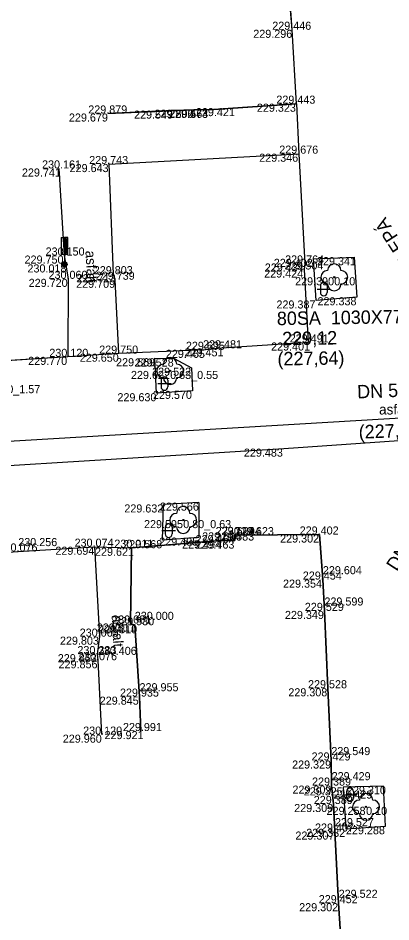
# Model space of a CAD drawing. Extents: x -599516 to -599132, y -1163668 to -1163119.
# Drawn here: x -599440.03 to -599426.15, y -1163390.89 to -1163357.26 of the extents above; entities that cross this region are included whole.
import ezdxf

# ---------------------------------------------------------------- set-up
doc = ezdxf.new("R2010")
doc.units = 0
for name, color, linetype in [('Bod-oznac1', 7, 'Continuous'), ('Bod-oznac2', 7, 'Continuous'), ('Bod-oznac3', 7, 'Continuous'), ('Bod-vyska1', 7, 'Continuous'), ('Bod-vyska2', 7, 'Continuous'), ('Bod-vyska3', 7, 'Continuous'), ('Z_cela-hrobu-horni-linie', 7, 'Continuous'), ('Z_chodnik', 7, 'Continuous'), ('Z_kanalizace-destova', 7, 'Continuous'), ('Z_komunikace', 7, 'Continuous'), ('Z_komunikace-osa', 7, 'Continuous'), ('Z_kultury-znacky', 7, 'Continuous'), ('Z_nove-stromy-prumer-kmene', 7, 'Continuous'), ('Z_obvod-kmene-spodek-ve-vysce1_2m', 7, 'Continuous'), ('Z_popis-budov-povrchu', 7, 'Continuous'), ('Z_stromy-kere', 7, 'Continuous'), ('Z_stromy-nove-vysazene', 7, 'Continuous'), ('Z_vodovod-bez-rozliseni', 7, 'Continuous'), ('Z_znacky-ostatni-orientacni-sloupek', 7, 'Continuous')]:
    doc.layers.add(name, color=color, linetype=linetype)

msp = doc.modelspace()

# ---------------------------------------------------------------- linework, layer by layer
at = {"layer": 'Bod-oznac1'}
for p, q in [((-599429.829, -1163357.692), (-599429.829, -1163357.692)), ((-599429.671, -1163360.443), (-599429.671, -1163360.443)), ((-599436.688, -1163360.808), (-599436.688, -1163360.808)), ((-599434.243, -1163360.699), (-599434.243, -1163360.699)), ((-599433.494, -1163360.666), (-599433.494, -1163360.666)), ((-599433.494, -1163360.668), (-599433.494, -1163360.668)), ((-599432.93, -1163360.669), (-599432.93, -1163360.669)), ((-599432.93, -1163360.67), (-599432.93, -1163360.67)), ((-599432.033, -1163360.607), (-599432.033, -1163360.607)), ((-599429.585, -1163362.303), (-599429.585, -1163362.303)), ((-599438.507, -1163362.853), (-599438.507, -1163362.853)), ((-599436.641, -1163362.689), (-599436.641, -1163362.689)), ((-599438.318, -1163366.094), (-599438.318, -1163366.094)), ((-599429.034, -1163366.216), (-599429.034, -1163366.216)), ((-599427.526, -1163366.153), (-599427.526, -1163366.153)), ((-599438.306, -1163366.424), (-599438.306, -1163366.424)), ((-599429.355, -1163366.389), (-599429.355, -1163366.389)), ((-599436.479, -1163366.789), (-599436.479, -1163366.789)), ((-599429.377, -1163366.613), (-599429.377, -1163366.613)), ((-599428.262, -1163366.902), (-599428.262, -1163366.902)), ((-599438.165, -1163366.961), (-599438.165, -1163366.961)), ((-599436.41, -1163366.995), (-599436.41, -1163366.995)), ((-599428.941, -1163367.765), (-599428.941, -1163367.765)), ((-599427.416, -1163367.646), (-599427.416, -1163367.646)), ((-599433.06, -1163369.603), (-599433.06, -1163369.603)), ((-599432.456, -1163369.546), (-599432.456, -1163369.546)), ((-599429.237, -1163369.33), (-599429.237, -1163369.33)), ((-599438.18, -1163369.864), (-599438.18, -1163369.864)), ((-599436.276, -1163369.746), (-599436.276, -1163369.746)), ((-599434.935, -1163369.915), (-599434.935, -1163369.915)), ((-599434.218, -1163369.927), (-599434.218, -1163369.927)), ((-599433.57, -1163370.268), (-599433.57, -1163370.268)), ((-599434.37, -1163370.388), (-599434.37, -1163370.388)), ((-599434.874, -1163371.217), (-599434.874, -1163371.217)), ((-599433.539, -1163371.129), (-599433.539, -1163371.129)), ((-599430.144, -1163373.279), (-599430.144, -1163373.279)), ((-599433.304, -1163375.288), (-599433.304, -1163375.288)), ((-599434.616, -1163375.356), (-599434.616, -1163375.356)), ((-599433.883, -1163375.939), (-599433.883, -1163375.939)), ((-599433.306, -1163376.589), (-599433.306, -1163376.589)), ((-599431.941, -1163376.496), (-599431.941, -1163376.496)), ((-599428.809, -1163376.476), (-599428.809, -1163376.476)), ((-599437.182, -1163376.93), (-599437.182, -1163376.93)), ((-599435.812, -1163376.968), (-599435.812, -1163376.968)), ((-599434.657, -1163376.687), (-599434.657, -1163376.687)), ((-599432.445, -1163376.697), (-599432.445, -1163376.697)), ((-599431.959, -1163376.701), (-599431.959, -1163376.701)), ((-599440.023, -1163377.108), (-599440.023, -1163377.108)), ((-599428.686, -1163378.154), (-599428.686, -1163378.154)), ((-599428.628, -1163379.319), (-599428.628, -1163379.319)), ((-599435.84, -1163379.788), (-599435.84, -1163379.788)), ((-599435.686, -1163379.853), (-599435.686, -1163379.853)), ((-599437.003, -1163380.277), (-599437.003, -1163380.277)), ((-599437.081, -1163380.928), (-599437.081, -1163380.928)), ((-599437.064, -1163381.155), (-599437.064, -1163381.155)), ((-599428.503, -1163382.198), (-599428.503, -1163382.198)), ((-599435.509, -1163382.509), (-599435.509, -1163382.509)), ((-599436.92, -1163383.924), (-599436.92, -1163383.924)), ((-599435.455, -1163383.791), (-599435.455, -1163383.791)), ((-599428.372, -1163384.886), (-599428.372, -1163384.886)), ((-599428.36, -1163385.82), (-599428.36, -1163385.82)), ((-599427.928, -1163385.885), (-599427.928, -1163385.885)), ((-599426.426, -1163385.84), (-599426.426, -1163385.84)), ((-599428.296, -1163386.505), (-599428.296, -1163386.505)), ((-599427.077, -1163386.61), (-599427.077, -1163386.61)), ((-599427.836, -1163387.428), (-599427.836, -1163387.428)), ((-599426.357, -1163387.332), (-599426.357, -1163387.332)), ((-599428.237, -1163387.531), (-599428.237, -1163387.531)), ((-599428.099, -1163390.196), (-599428.099, -1163390.196))]:
    msp.add_line(p, q, dxfattribs=at)
at = {"layer": 'Bod-oznac2'}
for p, q in [((-599429.829, -1163357.692), (-599429.829, -1163357.692)), ((-599429.671, -1163360.443), (-599429.671, -1163360.443)), ((-599436.688, -1163360.808), (-599436.688, -1163360.808)), ((-599429.585, -1163362.303), (-599429.585, -1163362.303)), ((-599438.507, -1163362.853), (-599438.507, -1163362.853)), ((-599436.641, -1163362.689), (-599436.641, -1163362.689)), ((-599438.318, -1163366.094), (-599438.318, -1163366.094)), ((-599429.355, -1163366.389), (-599429.355, -1163366.389)), ((-599436.479, -1163366.789), (-599436.479, -1163366.789)), ((-599429.377, -1163366.613), (-599429.377, -1163366.613)), ((-599438.165, -1163366.961), (-599438.165, -1163366.961)), ((-599436.41, -1163366.995), (-599436.41, -1163366.995)), ((-599433.06, -1163369.603), (-599433.06, -1163369.603)), ((-599432.456, -1163369.546), (-599432.456, -1163369.546)), ((-599429.237, -1163369.33), (-599429.237, -1163369.33)), ((-599438.18, -1163369.864), (-599438.18, -1163369.864)), ((-599436.276, -1163369.746), (-599436.276, -1163369.746)), ((-599431.941, -1163376.496), (-599431.941, -1163376.496)), ((-599428.809, -1163376.476), (-599428.809, -1163376.476)), ((-599437.182, -1163376.93), (-599437.182, -1163376.93)), ((-599435.812, -1163376.968), (-599435.812, -1163376.968)), ((-599432.445, -1163376.697), (-599432.445, -1163376.697)), ((-599431.959, -1163376.701), (-599431.959, -1163376.701)), ((-599440.023, -1163377.108), (-599440.023, -1163377.108)), ((-599428.686, -1163378.154), (-599428.686, -1163378.154)), ((-599428.628, -1163379.319), (-599428.628, -1163379.319)), ((-599435.84, -1163379.788), (-599435.84, -1163379.788)), ((-599435.686, -1163379.853), (-599435.686, -1163379.853)), ((-599437.003, -1163380.277), (-599437.003, -1163380.277)), ((-599437.081, -1163380.928), (-599437.081, -1163380.928)), ((-599437.064, -1163381.155), (-599437.064, -1163381.155)), ((-599428.503, -1163382.198), (-599428.503, -1163382.198)), ((-599435.509, -1163382.509), (-599435.509, -1163382.509)), ((-599436.92, -1163383.924), (-599436.92, -1163383.924)), ((-599435.455, -1163383.791), (-599435.455, -1163383.791)), ((-599428.372, -1163384.886), (-599428.372, -1163384.886)), ((-599428.36, -1163385.82), (-599428.36, -1163385.82)), ((-599428.296, -1163386.505), (-599428.296, -1163386.505)), ((-599428.237, -1163387.531), (-599428.237, -1163387.531)), ((-599428.099, -1163390.196), (-599428.099, -1163390.196))]:
    msp.add_line(p, q, dxfattribs=at)
at = {"layer": 'Bod-oznac3'}
for p, q in [((-599432.445, -1163376.697), (-599432.445, -1163376.697)), ((-599431.959, -1163376.701), (-599431.959, -1163376.701)), ((-599440.023, -1163377.108), (-599440.023, -1163377.108)), ((-599428.686, -1163378.154), (-599428.686, -1163378.154)), ((-599428.628, -1163379.319), (-599428.628, -1163379.319)), ((-599435.686, -1163379.853), (-599435.686, -1163379.853)), ((-599437.064, -1163381.155), (-599437.064, -1163381.155)), ((-599435.509, -1163382.509), (-599435.509, -1163382.509)), ((-599428.372, -1163384.886), (-599428.372, -1163384.886)), ((-599428.36, -1163385.82), (-599428.36, -1163385.82)), ((-599428.296, -1163386.505), (-599428.296, -1163386.505)), ((-599428.237, -1163387.531), (-599428.237, -1163387.531)), ((-599428.099, -1163390.196), (-599428.099, -1163390.196))]:
    msp.add_line(p, q, dxfattribs=at)
at = {"layer": 'Z_cela-hrobu-horni-linie'}
msp.add_line((-599438.507, -1163362.853), (-599438.318, -1163366.094), dxfattribs=at)
for points in [[(-599432.93, -1163360.669), (-599429.671, -1163360.443), (-599429.829, -1163357.692), (-599429.964, -1163356.071)], [(-599436.688, -1163360.808), (-599433.494, -1163360.666)], [(-599436.479, -1163366.789), (-599436.641, -1163362.689), (-599429.585, -1163362.303), (-599429.355, -1163366.389)], [(-599438.165, -1163366.961), (-599438.18, -1163369.864), (-599442.304, -1163370.125), (-599442.304, -1163370.125), (-599445.172, -1163370.369), (-599445.172, -1163370.369), (-599446.505, -1163370.421), (-599446.505, -1163370.421), (-599449.233, -1163370.571), (-599449.233, -1163370.571), (-599453.602, -1163370.813), (-599456.299, -1163370.964), (-599456.507, -1163366.584), (-599456.695, -1163363.936), (-599454.352, -1163363.803), (-599454.352, -1163363.803)], [(-599429.377, -1163366.613), (-599429.237, -1163369.33), (-599432.456, -1163369.546)], [(-599433.06, -1163369.603), (-599436.276, -1163369.746), (-599436.41, -1163366.995)], [(-599427.935, -1163392.862), (-599428.099, -1163390.196), (-599428.099, -1163390.196), (-599428.237, -1163387.531), (-599428.237, -1163387.531), (-599428.296, -1163386.505), (-599428.296, -1163386.505), (-599428.36, -1163385.82), (-599428.36, -1163385.82), (-599428.372, -1163384.886), (-599428.372, -1163384.886), (-599428.503, -1163382.198), (-599428.628, -1163379.319), (-599428.628, -1163379.319), (-599428.686, -1163378.154), (-599428.686, -1163378.154), (-599428.809, -1163376.476), (-599431.941, -1163376.496), (-599431.959, -1163376.701), (-599431.959, -1163376.701), (-599432.445, -1163376.697), (-599432.445, -1163376.697), (-599435.812, -1163376.968), (-599435.84, -1163379.788), (-599435.686, -1163379.853), (-599435.686, -1163379.853), (-599435.509, -1163382.509), (-599435.509, -1163382.509), (-599435.455, -1163383.791)], [(-599457.167, -1163381.242), (-599457.275, -1163378.053), (-599453.312, -1163377.791), (-599453.312, -1163377.791), (-599450.622, -1163377.661), (-599450.622, -1163377.661), (-599448.1, -1163377.528), (-599448.1, -1163377.528), (-599447.042, -1163377.458), (-599447.042, -1163377.458), (-599446.353, -1163377.412), (-599446.353, -1163377.412), (-599445.292, -1163377.409), (-599445.292, -1163377.409), (-599444.359, -1163377.36), (-599443.693, -1163377.321), (-599442.696, -1163377.276), (-599442.696, -1163377.276), (-599440.023, -1163377.108), (-599440.023, -1163377.108), (-599437.182, -1163376.93), (-599437.003, -1163380.277)], [(-599437.081, -1163380.928), (-599437.064, -1163381.155), (-599437.064, -1163381.155), (-599436.92, -1163383.924)]]:
    msp.add_lwpolyline(points, dxfattribs=at)
at = {"layer": 'Z_chodnik'}
for points in [[(-599429.671, -1163360.443), (-599432.033, -1163360.607), (-599432.93, -1163360.67), (-599433.494, -1163360.668), (-599434.243, -1163360.699), (-599436.688, -1163360.808)], [(-599436.276, -1163369.746), (-599436.41, -1163366.995), (-599436.479, -1163366.789), (-599436.641, -1163362.689), (-599429.585, -1163362.303)], [(-599438.507, -1163362.853), (-599438.318, -1163366.094), (-599438.165, -1163366.961), (-599438.18, -1163369.864)], [(-599437.182, -1163376.93), (-599437.003, -1163380.277), (-599437.081, -1163380.928), (-599437.064, -1163381.155), (-599436.92, -1163383.924)], [(-599435.455, -1163383.791), (-599435.509, -1163382.509), (-599435.686, -1163379.853), (-599435.84, -1163379.788), (-599435.812, -1163376.968)]]:
    msp.add_lwpolyline(points, dxfattribs=at)
at = {"layer": 'Z_kanalizace-destova'}
msp.add_line((-599488.219, -1163375.862), (-599421.433, -1163371.876), dxfattribs=at)
at = {"layer": 'Z_komunikace'}
for points in [[(-599429.671, -1163360.443), (-599429.829, -1163357.692), (-599429.934, -1163356.071), (-599428.132, -1163355.95), (-599428.177, -1163353.182), (-599430.089, -1163353.245), (-599430.127, -1163352.262), (-599430.194, -1163351.431), (-599430.23, -1163350.411), (-599430.239, -1163349.599), (-599430.253, -1163349.42), (-599430.372, -1163346.986), (-599430.362, -1163346.84), (-599430.439, -1163345.534), (-599430.624, -1163342.571), (-599433.698, -1163342.695)], [(-599429.671, -1163360.443), (-599429.585, -1163362.303), (-599429.355, -1163366.389), (-599429.377, -1163366.613), (-599429.237, -1163369.33)], [(-599429.034, -1163366.216), (-599427.526, -1163366.153), (-599427.416, -1163367.646), (-599428.941, -1163367.765), (-599429.034, -1163366.216)], [(-599429.237, -1163369.33), (-599432.456, -1163369.546), (-599433.06, -1163369.603), (-599436.276, -1163369.746), (-599438.18, -1163369.864), (-599440.264, -1163369.997), (-599442.304, -1163370.125), (-599445.172, -1163370.369), (-599446.505, -1163370.421), (-599449.233, -1163370.571)], [(-599434.874, -1163371.217), (-599434.935, -1163369.915), (-599434.218, -1163369.927), (-599433.57, -1163370.268), (-599433.539, -1163371.129), (-599434.874, -1163371.217)], [(-599433.304, -1163375.288), (-599433.306, -1163376.589), (-599434.657, -1163376.687), (-599434.616, -1163375.356)], [(-599433.304, -1163375.288), (-599434.616, -1163375.356)], [(-599457.275, -1163378.053), (-599453.312, -1163377.791), (-599450.622, -1163377.661), (-599448.1, -1163377.528), (-599447.042, -1163377.458), (-599446.353, -1163377.412), (-599445.292, -1163377.409), (-599444.359, -1163377.36), (-599444.351, -1163377.119), (-599443.689, -1163377.085), (-599443.693, -1163377.321), (-599442.696, -1163377.276), (-599440.023, -1163377.108), (-599437.182, -1163376.93), (-599435.812, -1163376.968), (-599432.445, -1163376.697), (-599431.959, -1163376.701), (-599431.941, -1163376.496), (-599428.809, -1163376.476)], [(-599428.809, -1163376.476), (-599428.686, -1163378.154), (-599428.628, -1163379.319), (-599428.503, -1163382.198), (-599428.372, -1163384.886), (-599428.36, -1163385.82), (-599428.296, -1163386.505), (-599428.237, -1163387.531), (-599428.099, -1163390.196), (-599427.935, -1163392.862)], [(-599426.357, -1163387.332), (-599426.426, -1163385.84), (-599427.928, -1163385.885), (-599427.836, -1163387.428), (-599426.357, -1163387.332)]]:
    msp.add_lwpolyline(points, dxfattribs=at)
at = {"layer": 'Z_komunikace-osa'}
msp.add_lwpolyline([(-599486.555, -1163376.352), (-599466.362, -1163375.334), (-599448.228, -1163374.387), (-599430.144, -1163373.279), (-599420.689, -1163372.612)], dxfattribs=at)
at = {"layer": 'Z_kultury-znacky'}
for p, q in [((-599428.777, -1163367.222), (-599428.777, -1163367.472)), ((-599428.527, -1163367.222), (-599428.527, -1163367.472)), ((-599428.902, -1163367.347), (-599428.402, -1163367.347)), ((-599434.833, -1163370.859), (-599434.333, -1163370.859)), ((-599434.708, -1163370.734), (-599434.708, -1163370.984)), ((-599434.458, -1163370.734), (-599434.458, -1163370.984)), ((-599434.675, -1163376.332), (-599434.175, -1163376.332)), ((-599434.55, -1163376.207), (-599434.55, -1163376.457)), ((-599434.3, -1163376.207), (-599434.3, -1163376.457)), ((-599427.801, -1163386.037), (-599427.801, -1163386.287)), ((-599427.551, -1163386.037), (-599427.551, -1163386.287)), ((-599427.926, -1163386.162), (-599427.426, -1163386.162))]:
    msp.add_line(p, q, dxfattribs=at)
for centre, start, end in [((-599428.653, -1163367.222), 0, 180), ((-599428.653, -1163367.472), 180, 0), ((-599434.584, -1163370.734), 0, 180), ((-599434.584, -1163370.984), 180, 0), ((-599434.425, -1163376.207), 0, 180), ((-599434.425, -1163376.457), 180, 0), ((-599427.676, -1163386.037), 0, 180), ((-599427.676, -1163386.287), 180, 0)]:
    msp.add_arc(centre, 0.125, start, end, dxfattribs=at)
at = {"layer": 'Z_stromy-kere'}
for centre in [(-599434.37, -1163370.388), (-599433.883, -1163375.939)]:
    msp.add_circle(centre, 0.025, dxfattribs=at)
for centre, start, end in [((-599434.37, -1163370.138), 0, 180), ((-599434.62, -1163370.388), 90, 270), ((-599434.12, -1163370.388), 270, 90), ((-599434.37, -1163370.638), 180, 0), ((-599433.883, -1163375.689), 0, 180), ((-599434.133, -1163375.939), 90, 270), ((-599433.633, -1163375.939), 270, 90), ((-599433.883, -1163376.189), 180, 0)]:
    msp.add_arc(centre, 0.25, start, end, dxfattribs=at)
at = {"layer": 'Z_stromy-nove-vysazene'}
for centre in [(-599428.262, -1163366.902), (-599427.077, -1163386.61)]:
    msp.add_circle(centre, 0.025, dxfattribs=at)
for centre, start, end in [((-599428.262, -1163366.652), 0, 180), ((-599428.512, -1163366.902), 90, 270), ((-599428.012, -1163366.902), 270, 90), ((-599428.262, -1163367.152), 180, 0), ((-599427.327, -1163386.61), 90, 270), ((-599427.077, -1163386.36), 0, 180), ((-599426.827, -1163386.61), 270, 90), ((-599427.077, -1163386.86), 180, 0)]:
    msp.add_arc(centre, 0.25, start, end, dxfattribs=at)
at = {"layer": 'Z_znacky-ostatni-orientacni-sloupek'}
for p, q in [((-599438.431, -1163365.424), (-599438.431, -1163366.049)), ((-599438.431, -1163365.424), (-599438.306, -1163365.424)), ((-599438.431, -1163366.049), (-599438.306, -1163366.049)), ((-599438.306, -1163366.049), (-599438.306, -1163366.324))]:
    msp.add_line(p, q, dxfattribs=at)
for points in [[(-599438.306, -1163366.049), (-599438.181, -1163366.049), (-599438.181, -1163365.424), (-599438.306, -1163365.424)], [(-599438.264, -1163366.007), (-599438.223, -1163366.007), (-599438.223, -1163365.467), (-599438.264, -1163365.467)]]:
    msp.add_lwpolyline(points, close=True, dxfattribs=at)
for radius in [0.1, 0.065, 0.03]:
    msp.add_circle((-599438.306, -1163366.424), radius, dxfattribs=at)

# ---------------------------------------------------------------- texts
at = {"layer": 'Bod-vyska1'}
for s, p in [('229.296', (-599431.276, -1163357.992)), ('229.323', (-599431.141, -1163360.743)), ('229.679', (-599438.137, -1163361.108)), ('229.549', (-599435.713, -1163360.999)), ('229.892', (-599434.953, -1163360.966)), ('229.506', (-599434.951, -1163360.968)), ('229.473', (-599434.413, -1163360.97)), ('229.564', (-599434.4, -1163360.969)), ('229.421', (-599433.411, -1163360.907)), ('229.346', (-599431.055, -1163362.603)), ('229.741', (-599439.886, -1163363.153)), ('229.643', (-599438.111, -1163362.989)), ('229.750', (-599439.788, -1163366.394)), ('229.402', (-599430.514, -1163366.516)), ('229.341', (-599428.904, -1163366.453)), ('230.018', (-599439.68, -1163366.724)), ('229.434', (-599430.848, -1163366.689)), ('229.713', (-599437.847, -1163367.089)), ('229.424', (-599430.87, -1163366.913)), ('229.390', (-599429.719, -1163367.202)), ('229.720', (-599439.635, -1163367.261)), ('229.709', (-599437.869, -1163367.295)), ('229.387', (-599430.413, -1163368.065)), ('229.338', (-599428.886, -1163367.946)), ('229.465', (-599434.53, -1163369.903)), ('229.451', (-599433.834, -1163369.846)), ('229.401', (-599430.613, -1163369.63)), ('229.770', (-599439.652, -1163370.164)), ('229.650', (-599437.733, -1163370.046)), ('229.569', (-599436.382, -1163370.215)), ('229.528', (-599435.688, -1163370.227)), ('229.522', (-599435.04, -1163370.568)), ('229.622', (-599435.829, -1163370.688)), ('229.630', (-599436.331, -1163371.517)), ('229.570', (-599435.009, -1163371.429)), ('229.483', (-599431.625, -1163373.579)), ('229.566', (-599434.751, -1163375.588)), ('229.632', (-599436.075, -1163375.656)), ('229.595', (-599435.342, -1163376.239)), ('229.495', (-599434.776, -1163376.889)), ('229.464', (-599433.422, -1163376.796)), ('229.302', (-599430.277, -1163376.776)), ('229.694', (-599438.641, -1163377.23)), ('229.621', (-599437.167, -1163377.268)), ('229.568', (-599436.116, -1163376.987)), ('229.494', (-599433.926, -1163376.997)), ('229.463', (-599433.429, -1163377.001)), ('229.354', (-599430.168, -1163378.454)), ('229.349', (-599430.098, -1163379.619)), ('229.811', (-599437.102, -1163380.088)), ('229.810', (-599437.05, -1163380.153)), ('229.803', (-599438.471, -1163380.577)), ('229.853', (-599438.551, -1163381.228)), ('229.856', (-599438.523, -1163381.455)), ('229.308', (-599429.971, -1163382.498)), ('229.845', (-599436.99, -1163382.809)), ('229.960', (-599438.366, -1163384.224)), ('229.921', (-599436.81, -1163384.091)), ('229.329', (-599429.831, -1163385.186)), ('229.309', (-599429.817, -1163386.12)), ('229.325', (-599429.398, -1163386.185)), ('229.310', (-599427.79, -1163386.14)), ('229.309', (-599429.753, -1163386.805)), ('229.258', (-599428.547, -1163386.91)), ('229.332', (-599429.306, -1163387.728)), ('229.288', (-599427.827, -1163387.632)), ('229.307', (-599429.707, -1163387.831)), ('229.302', (-599429.567, -1163390.496))]:
    msp.add_text(s, height=0.3, dxfattribs=at).set_placement(p)
at = {"layer": 'Bod-vyska2'}
for s, p in [('229.446', (-599430.57, -1163357.692)), ('229.443', (-599430.417, -1163360.443)), ('229.879', (-599437.418, -1163360.808)), ('229.676', (-599430.31, -1163362.303)), ('230.161', (-599439.137, -1163362.853)), ('229.743', (-599437.383, -1163362.689)), ('230.150', (-599439.005, -1163366.094)), ('229.764', (-599430.091, -1163366.389)), ('229.803', (-599437.213, -1163366.789)), ('229.504', (-599430.117, -1163366.613)), ('230.060', (-599438.897, -1163366.961)), ('229.739', (-599437.14, -1163366.995)), ('229.481', (-599433.145, -1163369.546)), ('229.491', (-599429.92, -1163369.33)), ('230.120', (-599438.867, -1163369.864)), ('229.750', (-599437.011, -1163369.746)), ('229.695', (-599433.784, -1163369.603)), ('229.624', (-599432.676, -1163376.496)), ('229.402', (-599429.549, -1163376.476)), ('230.074', (-599437.927, -1163376.93)), ('230.011', (-599436.447, -1163376.968)), ('229.604', (-599433.179, -1163376.697)), ('229.583', (-599432.694, -1163376.701)), ('230.076', (-599440.757, -1163377.108)), ('229.454', (-599429.432, -1163378.154)), ('229.529', (-599429.357, -1163379.319)), ('230.001', (-599436.526, -1163379.788)), ('229.930', (-599436.414, -1163379.853)), ('230.063', (-599437.736, -1163380.277)), ('230.383', (-599437.821, -1163380.928)), ('230.076', (-599437.798, -1163381.155)), ('229.528', (-599429.238, -1163382.198)), ('229.935', (-599436.238, -1163382.509)), ('230.120', (-599437.607, -1163383.924)), ('229.991', (-599436.127, -1163383.791)), ('229.429', (-599429.107, -1163384.886)), ('229.389', (-599429.089, -1163385.82)), ('229.389', (-599429.025, -1163386.505)), ('229.407', (-599428.978, -1163387.531)), ('229.452', (-599428.84, -1163390.196))]:
    msp.add_text(s, height=0.3, dxfattribs=at).set_placement(p)
at = {"layer": 'Bod-vyska3'}
for s, p in [('230.094', (-599432.445, -1163376.497)), ('229.623', (-599431.959, -1163376.501)), ('230.256', (-599440.023, -1163376.908)), ('229.604', (-599428.686, -1163377.954)), ('229.599', (-599428.628, -1163379.119)), ('230.000', (-599435.686, -1163379.653)), ('230.406', (-599437.064, -1163380.955)), ('229.955', (-599435.509, -1163382.309)), ('229.549', (-599428.372, -1163384.686)), ('229.429', (-599428.36, -1163385.62)), ('229.429', (-599428.296, -1163386.305)), ('229.527', (-599428.237, -1163387.331)), ('229.522', (-599428.099, -1163389.996))]:
    msp.add_text(s, height=0.3, dxfattribs=at).set_placement(p)
at = {"layer": 'Z_kanalizace-destova'}
for s, rotation, p in [('DN 300 SLEPÁ', 122.9508, (-599423.851, -1163368.507)), ('DN 500', 2.1906, (-599427.4, -1163371.413)), ('(227,46)', 2.1906, (-599427.343, -1163372.912)), ('DN 300 SLEPÁ', 57.0492, (-599425.939, -1163377.871))]:
    msp.add_text(s, height=0.5, rotation=rotation, dxfattribs=at).set_placement(p)
at = {"layer": 'Z_nove-stromy-prumer-kmene'}
for p in [(-599428.262, -1163367.202), (-599427.077, -1163386.91)]:
    msp.add_text('0.10', height=0.3, dxfattribs=at).set_placement(p)
at = {"layer": 'Z_obvod-kmene-spodek-ve-vysce1_2m'}
for s, p in [('0.63_0.55', (-599434.37, -1163370.688)), ('2.20_1.57', (-599440.988, -1163371.217)), ('0.80_0.63', (-599433.883, -1163376.239))]:
    msp.add_text(s, height=0.3, dxfattribs=at).set_placement(p)
at = {"layer": 'Z_popis-budov-povrchu'}
for p in [(-599437.523, -1163365.92), (-599436.552, -1163379.483)]:
    msp.add_text('asfalt', height=0.375, rotation=273.4503, dxfattribs=at).set_placement(p)
msp.add_text('asfalt', height=0.375, dxfattribs=at).set_placement((-599426.593, -1163372.009))
at = {"layer": 'Z_vodovod-bez-rozliseni'}
for s, p in [('80SA  1030X770', (-599430.394, -1163368.687)), (' 229,12', (-599430.382, -1163369.437)), ('(227,64) ', (-599430.371, -1163370.187))]:
    msp.add_text(s, height=0.5, rotation=0.8872, dxfattribs=at).set_placement(p)

doc.saveas('drawing.dxf')
